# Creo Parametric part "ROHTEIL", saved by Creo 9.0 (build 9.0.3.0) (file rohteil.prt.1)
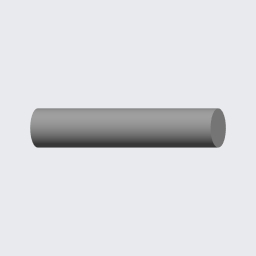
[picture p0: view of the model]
Materials in the file: S235JRG2

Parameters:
  BENENNUNG = "XXX"
  DATUM = "XX.XX.XX"
  ERSTELLER = "ARINDA"
  TEILETYP = "Fertigungsteil"
  PTC_MASTER_MATERIAL = "S235JRG2"
  SELECT_EN_NAME = "S235JRG2"
  SELECT_DIN_NAME = "RSt37-2"
  SELECT_DIN_NUMBER = "1.0038"
  SELECT_ASTM_NAME = "A 283 M Grade 2"
  MATERIAL_GROUP = "ME_ST_Baustahl"
  STANDARD_EN_DELIVERYSPEC = "DIN EN 10025"
  STANDARD_DIN_DELIVERYSPEC = "DIN 17100"

Other parameters: MASSE

Created from: ARINDA-STARTTEIL.PRT

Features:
  1. coordinate system "CS0"
  2. datum plane "DTM1", "T_RECHTS_Y-Z"
  3. datum plane "DTM2", "T_OBEN_X-Z"
  4. datum plane "DTM3", "T_VORNE_X-Y"
  5. datum axis "T_X-ACHSE"
  6. datum axis "A_1"
  7. datum axis "A_2"
  8. revolve "Drehen 1"

Other named items: T_BASIC, T_Y-ACHSE, T_Z-ACHSE

Layers: 00_STD-ACHSEN, 00_STD-EBENEN, 00_STD-KOORDSYS, VOLUMENGEOMETRIE

Surfaces: 2 plane, 2 cylinder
